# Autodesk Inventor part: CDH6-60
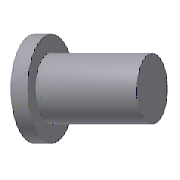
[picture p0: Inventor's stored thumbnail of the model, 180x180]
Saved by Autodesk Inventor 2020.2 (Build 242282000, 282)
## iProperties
Manager: www.cadconsulting.pl
Company: Fabian Stasiak CAD Consulting
Created: 2014-02
Part Number: CDH6-60
Material: SKD61
Description: Straight Core Pin
Document SubType Name: Modeling
Designer: F.Stasiak
Standard Revision: 1
Manufacturer: PUNCH
Language: pl-PL
Size Designation: 6-60
Categories: <MemberInstance><Categories><Category DisplayName="Forma wtryskowa" InternalName="349578f2-f4d4-4954-8c09-8e99297a61c0" Mnemonic="MOLD"><Category DisplayName="W
Mass: 1.61494 g
Surface Area: 11.4822 cm^2
Volume: 1.61494 cm^3
Density: 7.8 g/cm^3
Appearance: Aluminium - ciemne
Catalog Web Link: www.expertbooks.pl
IsCustomPart: 1
Author: F.Stasiak
Subject: Zbiór ćwiczeń. Autodesk Inventor 2020. Kurs Professional
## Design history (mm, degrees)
sketch "Sketch1"
  geometry: L1 (4.5, 0)-(4.5, 4); L2 (4.5, 4)-(3, 4); L3 (3, 4)-(3, 60); L4 (3, 60)-(0, 60); L5 (4.5, 0)-(0, 0); L6 (0, 0)-(0, 60); L7 (0, 60)-(0, -10) reference; 1 further point
  constraints: 14 end point, 2 horizontal, 1 coincident, 1 collinear, 1 parallel
  dimensions: "d2" = 4 distance of L1.start L1.end (= T_); "d19" = 60 distance between parallel lines of L4 L5 (= L); "d38" = 6 diameter of L3 L7 (= P); "d39" = 9 diameter of L1 L7 (= H_)
revolve "Revolution1" sketch "Sketch1" stored, may be unused: angle "d4" = 90 deg
fillet "Fillet1" dims "d36" = 0.3
workplane "Work Plane1"
sketch "Sketch2"
  geometry: 2 further points
  constraints: 1 vertical alignment
  dimensions: "d21" = 2 distance of point (0, -2) point (0, 0) (= 0.5 x T_)
hole "Anti_Rotary Hole" sketch "Sketch2" at (0, 0) diameter "d22" = 0.8 (= Anti_Rotary_D); stored, may be unused: countersink angle "d26" = 90 deg, drill point angle "d28" = 118 deg; dims "d23" = 6, "d24" = 4, "d25" = 2, "d27" = 1.2 (= 1.5 x Anti_Rotary_D)
sketch "Sketch3"
  geometry: L1 (-3.3, 3.059)-(-3.3, -3.059); A1 r 4.5 centre (0, 0) between (-3.3, 3.059) and (-3.3, -3.059) reference; 1 further point
  constraints: 2 end point, 2 point on circle, 1 vertical
  dimensions: "d29" = 3.3 distance from line of point (0, 0) L1 (= Anti_Rotary_P)
extrude "Anti_Rotary Plane" cut sketch "Sketch3" extent not by distance; stored distance "d30" = 10; taper "d31" = 0 deg
feature "Rzeźbienie3"
body "Solid1"
feature "Powierzchnia3"
body "Srf3"
other parameters: "H_" = 9 [user parameter; used in 1 equation term], "L" = 60 [user parameter; used in 1 equation term], "P" = 6 [user parameter; used in 1 equation term], "d7" = 0, "d8" = 0, "T_" = 4 [user parameter; used in 2 equation terms], "Anti_Rotary_P" = 3.3 [user parameter; used in 1 equation term], "Anti_Rotary_D" = 0.8 [user parameter; used in 2 equation terms], "d32" = 0, "d33" = 0, "d34" = 0, "d35" = 0, "IsARPlane" = 0 [user parameter], "IsARHole" = 0 [user parameter]
